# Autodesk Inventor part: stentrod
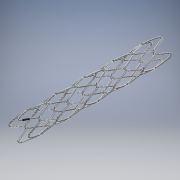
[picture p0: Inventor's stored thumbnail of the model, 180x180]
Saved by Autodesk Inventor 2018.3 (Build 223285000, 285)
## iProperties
Created: 2013-10
Part Number: stentrod
Material: Generic
Document SubType Name: Modeling
Designer: Warren
Density: 1 g/cm^3
Appearance: Chrome - Polished
Author: Warren
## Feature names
1. Sweep1
2. Mirror1
3. Rectangular Pattern1
## Parameters: d0 = 0.2545 mm, d11 = 0.125 mm, d12 = 0.125 mm, d13 = 0.05 mm, d14 = 0.1 mm, d15 = 0.2 mm, d16 = 0.2 mm, d17 = 0.05 mm, d18 = 0.2 mm, d19 = 0.2 mm, d20 = 0.05 mm, d21 = 0.2 mm, d22 = 0.2 mm, d23 = 0.05 mm, d24 = 0.2 mm, d25 = 0.2 mm, d26 = 0, d29 = 0.75 mm, d30 = 0.035 mm, d32 = 0
